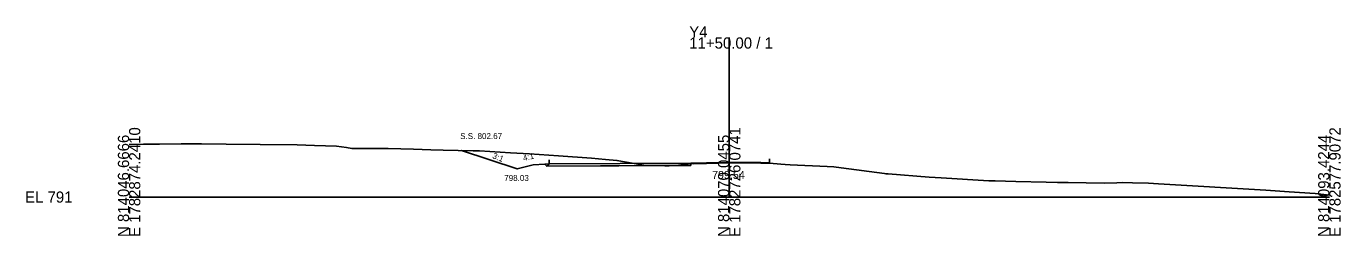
# Model space of a CAD drawing. Extents: x -26 to 3903, y -10 to 9562.
# Drawn here: x -25.7 to 302.8, y 3490.3 to 3542.8 of the extents above; entities that cross this region are included whole.
import ezdxf

# ---------------------------------------------------------------- set-up
doc = ezdxf.new("R2010")
doc.units = 0
for name, color, linetype in [('Exist Cross Section Cell', 7, 'Continuous'), ('Exist XS Center Line Elevation Label', 7, 'Continuous'), ('Exist XS Ground Line', 7, 'Continuous'), ('Prop XS Ditch Slope Text', 7, 'Continuous'), ('Prop XS Ditch Standard Text', 7, 'Continuous'), ('Prop XS Dump Level', 7, 'Continuous'), ('Prop XS Earthwork Shape', 7, 'Continuous'), ('Prop XS EOT Tick Mark', 7, 'Continuous'), ('Prop XS Finish Grade', 7, 'Continuous'), ('Prop XS Finish Grade Earthwork', 7, 'Continuous'), ('Prop XS Finish Grade Pavement', 7, 'Continuous'), ('Prop XS Pvmt Edge Slope', 7, 'Continuous'), ('Prop XS Side Slope Text', 7, 'Continuous'), ('Prop XS SS Elevation Text', 7, 'Continuous'), ('Prop XS Subgrade Earthwork', 7, 'Continuous')]:
    doc.layers.add(name, color=color, linetype=linetype)

msp = doc.modelspace()

# ---------------------------------------------------------------- linework, layer by layer
at = {"layer": 'Exist Cross Section Cell'}
for p, q in [((150, 3500), (150, 3539.98)), ((0, 3500), (150, 3500)), ((150, 3500), (300, 3500))]:
    msp.add_line(p, q, dxfattribs=at)
at = {"layer": 'Exist XS Ground Line'}
for p, q in [((0, 3513.19), (3.59, 3513.22)), ((3.59, 3513.22), (7.63, 3513.26)), ((7.63, 3513.26), (12.99, 3513.33)), ((12.99, 3513.33), (18.06, 3513.3)), ((18.06, 3513.3), (24.24, 3513.25)), ((24.24, 3513.25), (32.73, 3513.16)), ((32.73, 3513.16), (42.05, 3513.09)), ((42.05, 3513.09), (46.37, 3512.95)), ((46.37, 3512.95), (51.81, 3512.76)), ((51.81, 3512.76), (54.33, 3512.37)), ((54.33, 3512.37), (55.68, 3512.14)), ((55.68, 3512.14), (59.62, 3512.18)), ((59.62, 3512.18), (64.78, 3512.2)), ((64.78, 3512.2), (71.09, 3511.97)), ((71.09, 3511.97), (75.46, 3511.84)), ((75.46, 3511.84), (78.52, 3511.77)), ((78.52, 3511.77), (86.02, 3511.6)), ((86.02, 3511.6), (87.57, 3511.55)), ((87.57, 3511.55), (95.34, 3511.07)), ((95.34, 3511.07), (100.06, 3510.81)), ((100.06, 3510.81), (107.33, 3510.36)), ((107.33, 3510.36), (115.57, 3509.74)), ((115.57, 3509.74), (119.09, 3509.43)), ((119.09, 3509.43), (121.95, 3509.19)), ((121.95, 3509.19), (128.15, 3508.05)), ((128.15, 3508.05), (128.64, 3507.95)), ((128.64, 3507.95), (133.87, 3507.79)), ((133.87, 3507.79), (135.03, 3507.79)), ((135.03, 3507.79), (136.63, 3507.94)), ((136.63, 3507.94), (140.38, 3508.39)), ((140.38, 3508.39), (144.3, 3508.41)), ((144.3, 3508.41), (150.12, 3508.55)), ((150.12, 3508.55), (157.94, 3508.51)), ((157.94, 3508.51), (160.08, 3508.48)), ((160.08, 3508.48), (162.91, 3508.22)), ((162.91, 3508.22), (163.99, 3508.13)), ((163.99, 3508.13), (165.21, 3508.09)), ((165.21, 3508.09), (174.47, 3507.69)), ((174.47, 3507.69), (176.11, 3507.57)), ((176.11, 3507.57), (177.98, 3507.3)), ((177.98, 3507.3), (188.8, 3505.89)), ((188.8, 3505.89), (189.13, 3505.84)), ((189.13, 3505.84), (189.73, 3505.8)), ((189.73, 3505.8), (199.99, 3504.97)), ((199.99, 3504.97), (202.96, 3504.78)), ((202.96, 3504.78), (214.89, 3504.1)), ((214.89, 3504.1), (215.62, 3504.08)), ((215.62, 3504.08), (216.48, 3504.05)), ((216.48, 3504.05), (221.6, 3503.86)), ((221.6, 3503.86), (229.24, 3503.73)), ((229.24, 3503.73), (232.08, 3503.68)), ((232.08, 3503.68), (234.75, 3503.64)), ((234.75, 3503.64), (243.7, 3503.46)), ((243.7, 3503.46), (246.87, 3503.55)), ((246.87, 3503.55), (248.27, 3503.61)), ((248.27, 3503.61), (250.78, 3503.59)), ((250.78, 3503.59), (254.81, 3503.47)), ((254.81, 3503.47), (257.29, 3503.29)), ((257.29, 3503.29), (284.09, 3501.74)), ((284.09, 3501.74), (289.97, 3501.34)), ((289.97, 3501.34), (296.46, 3500.86)), ((296.46, 3500.86), (300, 3500.51))]:
    msp.add_line(p, q, dxfattribs=at)
at = {"layer": 'Prop XS Earthwork Shape'}
for points in [[(83.1, 3511.67), (86.02, 3511.6), (87.57, 3511.55), (95.34, 3511.07), (100.06, 3510.81), (107.33, 3510.36), (115.57, 3509.74), (119.09, 3509.43), (121.95, 3509.19), (128.15, 3508.05), (128.64, 3507.95), (131.12, 3507.87), (104.41, 3507.71), (103.9, 3508.22), (101, 3508.03), (97, 3507.03)], [(136.24, 3507.9), (131.12, 3507.87), (133.87, 3507.79), (135.03, 3507.79)], [(136.24, 3507.9), (136.63, 3507.94), (140.38, 3508.39), (140.38, 3507.97), (140.38, 3507.93)]]:
    msp.add_lwpolyline(points, close=True, dxfattribs=at)
at = {"layer": 'Prop XS EOT Tick Mark'}
for p, q in [((105, 3508.3), (105, 3509.3)), ((105, 3508.3), (105, 3509.3)), ((160.08, 3508.61), (160.08, 3509.61))]:
    msp.add_line(p, q, dxfattribs=at)
at = {"layer": 'Prop XS Finish Grade'}
msp.add_line((105, 3508.3), (103.9, 3508.22), dxfattribs=at)
at = {"layer": 'Prop XS Finish Grade Earthwork'}
for p, q in [((97, 3507.03), (83.1, 3511.67)), ((101, 3508.03), (97, 3507.03)), ((101, 3508.03), (97, 3507.03)), ((103.9, 3508.22), (101, 3508.03))]:
    msp.add_line(p, q, dxfattribs=at)
at = {"layer": 'Prop XS Finish Grade Pavement'}
for p, q in [((140.38, 3508.51), (105, 3508.3)), ((140.38, 3508.51), (105, 3508.3)), ((140.38, 3508.51), (144.29, 3508.54)), ((140.38, 3508.51), (140.4, 3508.39)), ((140.38, 3508.51), (140.4, 3508.39)), ((144.29, 3508.54), (150.11, 3508.67)), ((150.12, 3508.67), (157.94, 3508.63)), ((157.94, 3508.63), (160.08, 3508.61))]:
    msp.add_line(p, q, dxfattribs=at)
at = {"layer": 'Prop XS Pvmt Edge Slope'}
for q in [(104.41, 3507.71), (104.46, 3507.75)]:
    msp.add_line((105, 3508.3), q, dxfattribs=at)
at = {"layer": 'Prop XS Subgrade Earthwork'}
for p, q in [((104.41, 3507.71), (103.9, 3508.22)), ((140.38, 3507.93), (104.41, 3507.71)), ((140.38, 3507.97), (140.38, 3508.39)), ((140.38, 3507.93), (140.38, 3508.39))]:
    msp.add_line(p, q, dxfattribs=at)

# ---------------------------------------------------------------- texts
at = {"layer": 'Exist Cross Section Cell'}
for s, p in [('Y4', (140, 3539.98)), ('11+50.00 / 1', (140, 3537.18)), ('EL 791', (-26, 3498.6))]:
    msp.add_text(s, height=2.8, dxfattribs=at).set_placement(p)
for s, p in [('N 814046.6666', (0, 3490)), ('E 1782874.2410', (2.8, 3490)), ('N 814070.0455', (150, 3490)), ('E 1782726.0741', (152.8, 3490)), ('N 814093.4244', (300, 3490)), ('E 1782577.9072', (302.8, 3490))]:
    msp.add_text(s, height=2.8, rotation=90, dxfattribs=at).set_placement(p)
at = {"layer": 'Exist XS Center Line Elevation Label'}
msp.add_text('799.54', height=2, dxfattribs=at).set_placement((145.72, 3504.54))
at = {"layer": 'Prop XS Ditch Slope Text'}
msp.add_text('4:1', height=1.5, rotation=14.0362, dxfattribs=at).set_placement((98.64, 3508.99))
msp.add_text('4:1', height=1.5, rotation=14.0362, dxfattribs=at).set_placement((98.64, 3508.99))
at = {"layer": 'Prop XS Ditch Standard Text'}
msp.add_text('798.03', height=1.5, dxfattribs=at).set_placement((93.77, 3504.03))
msp.add_text('798.03', height=1.5, dxfattribs=at).set_placement((93.77, 3504.03))
at = {"layer": 'Prop XS Dump Level'}
for s, height, p in [('Case1', 0.04, (101, 3507.99)), ('Case1', 0.04, (101, 3507.99)), ('Eop', 0.3, (140.38, 3508.09)), ('Eop', 0.3, (140.38, 3508.09))]:
    msp.add_text(s, height=height, dxfattribs=at).set_placement(p)
at = {"layer": 'Prop XS Side Slope Text'}
msp.add_text('3:1', height=1.5, rotation=338.5931, dxfattribs=at).set_placement((90.69, 3509.76))
at = {"layer": 'Prop XS SS Elevation Text'}
msp.add_text('S.S. 802.67', height=1.5, dxfattribs=at).set_placement((82.76, 3514.52))

doc.saveas('drawing.dxf')
